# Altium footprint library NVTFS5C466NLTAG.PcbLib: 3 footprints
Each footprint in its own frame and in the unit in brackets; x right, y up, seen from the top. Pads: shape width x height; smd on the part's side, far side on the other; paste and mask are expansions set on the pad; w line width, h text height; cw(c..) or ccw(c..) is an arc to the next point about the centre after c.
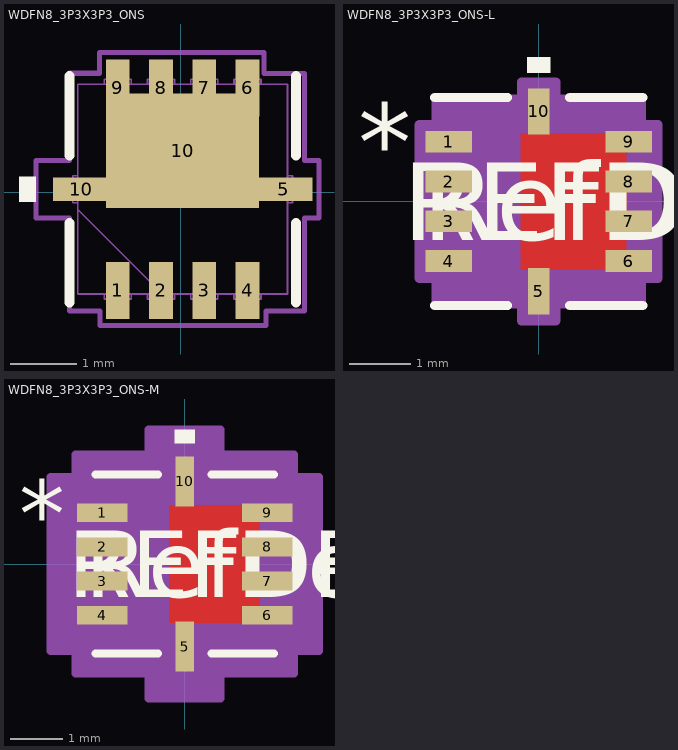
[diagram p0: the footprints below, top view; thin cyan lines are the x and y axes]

## WDFN8_3P3X3P3_ONS [mm]
pads (11):
  rect 0.356x0.859 smd paste+0 mask+0: 1(-0.948,-1.474) 2(-0.298,-1.474) 3(0.352,-1.474) 4(1.002,-1.474) 6(1.002,1.569) 7(0.352,1.569) 8(-0.298,1.569) 9(-0.948,1.569)
  rect 0.859x0.356 smd paste+0 mask+0: 5(1.548,0.047) 10(-1.495,0.047)
  rect 2.3x1.725 smd: 10(0.025,0.625)
Top Overlay:
  region: -2.178,0.238 -2.178,-0.143 -2.432,-0.143 -2.432,0.238
  lines w0.152: -1.675,-1.655 -1.675,-0.464 ; -1.675,0.558 -1.675,1.749 ; 1.728,-1.655 1.728,-0.464 ; 1.728,0.558 1.728,1.749
Top Paste:
  region: 1.144,-0.245 -1.091,-0.245 -1.091,1.482 1.144,1.482
Top Solder:
  region: 1.144,-0.245 -1.091,-0.245 -1.091,1.482 1.144,1.482
Mechanical 13:
  lines w0.025: -1.548,-0.258 -0.278,-1.528 ; -1.624,-0.156 -1.548,-0.156 -1.548,0.25 -1.624,0.25 -1.624,-0.156 ; -1.548,-1.528 -1.548,1.622 1.601,1.622 1.601,-1.528 -1.548,-1.528 ; -1.152,-1.604 -1.152,-1.528 -0.745,-1.528 -0.745,-1.604 -1.152,-1.604 ; -1.152,1.622 -0.745,1.622 -0.745,1.698 -1.152,1.698 -1.152,1.622 ; -0.502,-1.604 -0.502,-1.528 -0.095,-1.528 -0.095,-1.604 -0.502,-1.604 ; -0.502,1.622 -0.502,1.698 -0.095,1.698 -0.095,1.622 -0.502,1.622 ; 0.148,-1.604 0.148,-1.528 0.555,-1.528 0.555,-1.604 0.148,-1.604 ; 0.148,1.622 0.148,1.698 0.555,1.698 0.555,1.622 0.148,1.622 ; 0.798,-1.604 0.798,-1.528 1.205,-1.528 1.205,-1.604 0.798,-1.604 ; 0.798,1.622 0.798,1.698 1.205,1.698 1.205,1.622 0.798,1.622 ; 1.601,-0.156 1.601,0.25 1.678,0.25 1.678,-0.156 1.601,-0.156
Mechanical 15:
  lines w0.076: -2.178,-0.385 -1.675,-0.385 -1.675,-1.782 -1.213,-1.782 -1.213,-2 1.28,-2 1.28,-1.782 1.855,-1.782 1.855,-0.385 2.075,-0.385 2.075,0.479 1.855,0.479 1.855,1.786 1.25,1.786 1.25,2.1 -1.225,2.1 -1.225,1.789 -1.675,1.789 -1.675,0.479 -2.178,0.479 -2.178,-0.385
3D body "WDFN8_3P3X3P3_ONS.step": height 0.81, standoff 0, extent -1.624,-1.604 1.678,1.698

## WDFN8_3P3X3P3_ONS-L [mm]
pads (10):
  rect 0.759x0.356 smd paste+0 mask+0: 1(-1.472,0.975) 2(-1.472,0.325) 3(-1.472,-0.325) 4(-1.472,-0.975) 6(1.472,-0.975) 7(1.472,-0.325) 8(1.472,0.325) 9(1.472,0.975)
  rect 0.356x0.759 smd paste+0 mask+0: 5(0,-1.472) 10(0,1.472)
Top Layer:
  region: -0.292,-1.118 -0.292,1.118 1.435,1.118 1.435,-1.118
Top Overlay:
  region: 0.191,2.105 -0.191,2.105 -0.191,2.359 0.191,2.359
  lines w0.152: -1.702,-1.702 -0.511,-1.702 ; -1.702,1.702 -0.511,1.702 ; 0.511,-1.702 1.702,-1.702 ; 0.511,1.702 1.702,1.702
  text "*" at -2.956,0.34 h1.27
  text "RefDes" at -1.905,-0.635 h1.27
  text "REFDES" at -2.222,-0.635 h1.27
Top Paste:
  region: -0.292,-1.118 -0.292,1.118 1.435,1.118 1.435,-1.118
Top Solder:
  region: -0.292,-1.118 -0.292,1.118 1.435,1.118 1.435,-1.118
Mechanical 13:
  lines w0.025: -1.575,0.305 -0.305,1.575 ; -1.651,-1.178 -1.651,-0.772 -1.575,-0.772 -1.575,-1.178 -1.651,-1.178 ; -1.651,-0.528 -1.651,-0.122 -1.575,-0.122 -1.575,-0.528 -1.651,-0.528 ; -1.651,0.122 -1.651,0.528 -1.575,0.528 -1.575,0.122 -1.651,0.122 ; -1.651,0.772 -1.651,1.178 -1.575,1.178 -1.575,0.772 -1.651,0.772 ; -1.575,-1.575 1.575,-1.575 1.575,1.575 -1.575,1.575 -1.575,-1.575 ; -0.203,-1.651 -0.203,-1.575 0.203,-1.575 0.203,-1.651 -0.203,-1.651 ; -0.203,1.575 0.203,1.575 0.203,1.651 -0.203,1.651 -0.203,1.575 ; 1.575,-1.178 1.575,-0.772 1.651,-0.772 1.651,-1.178 1.575,-1.178 ; 1.575,-0.528 1.575,-0.122 1.651,-0.122 1.651,-0.528 1.575,-0.528 ; 1.575,0.122 1.575,0.528 1.651,0.528 1.651,0.122 1.575,0.122 ; 1.575,0.772 1.575,1.178 1.651,1.178 1.651,0.772 1.575,0.772
  text "*" at -0.622,0.34 h1.27
  text "RefDes2" at -2.222,-0.635 h1.27
Mechanical 15:
  region: -0.28,-1.676 -1.676,-1.676 -1.676,-1.255 -1.953,-1.255 -1.953,1.255 -1.676,1.255 -1.676,1.676 -0.28,1.676 -0.28,1.953 0.28,1.953 0.28,1.676 1.676,1.676 1.676,1.255 1.953,1.255 1.953,-1.255 1.676,-1.255 1.676,-1.676 0.28,-1.676 0.28,-1.953 -0.28,-1.953
  lines w0.152: -1.953,-1.255 -1.676,-1.255 -1.676,-1.676 -0.28,-1.676 -0.28,-1.953 0.28,-1.953 0.28,-1.676 1.676,-1.676 1.676,-1.255 1.953,-1.255 1.953,1.255 1.676,1.255 1.676,1.676 0.28,1.676 0.28,1.953 -0.28,1.953 -0.28,1.676 -1.676,1.676 -1.676,1.255 -1.953,1.255 -1.953,-1.255
3D body "WDFN8_3P3X3P3_ONS.step": height 0.81, standoff 0, extent -1.651,-1.651 1.651,1.651

## WDFN8_3P3X3P3_ONS-M [mm]
pads (10):
  rect 0.959x0.356 smd paste+0 mask+0: 1(-1.572,0.975) 2(-1.572,0.325) 3(-1.572,-0.325) 4(-1.572,-0.975) 6(1.572,-0.975) 7(1.572,-0.325) 8(1.572,0.325) 9(1.572,0.975)
  rect 0.356x0.959 smd paste+0 mask+0: 5(0,-1.572) 10(0,1.572)
Top Layer:
  region: -0.292,-1.118 -0.292,1.118 1.435,1.118 1.435,-1.118
Top Overlay:
  region: 0.191,2.305 -0.191,2.305 -0.191,2.559 0.191,2.559
  lines w0.152: -1.702,-1.702 -0.511,-1.702 ; -1.702,1.702 -0.511,1.702 ; 0.511,-1.702 1.702,-1.702 ; 0.511,1.702 1.702,1.702
  text "*" at -3.156,0.34 h1.27
  text "RefDes" at -1.905,-0.635 h1.27
  text "REFDES" at -2.222,-0.635 h1.27
Top Paste:
  region: -0.292,-1.118 -0.292,1.118 1.435,1.118 1.435,-1.118
Top Solder:
  region: -0.292,-1.118 -0.292,1.118 1.435,1.118 1.435,-1.118
Mechanical 13:
  lines w0.025: -1.575,0.305 -0.305,1.575 ; -1.651,-1.178 -1.651,-0.772 -1.575,-0.772 -1.575,-1.178 -1.651,-1.178 ; -1.651,-0.528 -1.651,-0.122 -1.575,-0.122 -1.575,-0.528 -1.651,-0.528 ; -1.651,0.122 -1.651,0.528 -1.575,0.528 -1.575,0.122 -1.651,0.122 ; -1.651,0.772 -1.651,1.178 -1.575,1.178 -1.575,0.772 -1.651,0.772 ; -1.575,-1.575 1.575,-1.575 1.575,1.575 -1.575,1.575 -1.575,-1.575 ; -0.203,-1.651 -0.203,-1.575 0.203,-1.575 0.203,-1.651 -0.203,-1.651 ; -0.203,1.575 0.203,1.575 0.203,1.651 -0.203,1.651 -0.203,1.575 ; 1.575,-1.178 1.575,-0.772 1.651,-0.772 1.651,-1.178 1.575,-1.178 ; 1.575,-0.528 1.575,-0.122 1.651,-0.122 1.651,-0.528 1.575,-0.528 ; 1.575,0.122 1.575,0.528 1.651,0.528 1.651,0.122 1.575,0.122 ; 1.575,0.772 1.575,1.178 1.651,1.178 1.651,0.772 1.575,0.772
  text "*" at -0.622,0.34 h1.27
  text "RefDes2" at -2.222,-0.635 h1.27
Mechanical 15:
  region: -0.686,-2.083 -2.083,-2.083 -2.083,-1.661 -2.559,-1.661 -2.559,1.661 -2.083,1.661 -2.083,2.083 -0.686,2.083 -0.686,2.559 0.686,2.559 0.686,2.083 2.083,2.083 2.083,1.661 2.559,1.661 2.559,-1.661 2.083,-1.661 2.083,-2.083 0.686,-2.083 0.686,-2.559 -0.686,-2.559
  lines w0.152: -2.559,-1.661 -2.083,-1.661 -2.083,-2.083 -0.686,-2.083 -0.686,-2.559 0.686,-2.559 0.686,-2.083 2.083,-2.083 2.083,-1.661 2.559,-1.661 2.559,1.661 2.083,1.661 2.083,2.083 0.686,2.083 0.686,2.559 -0.686,2.559 -0.686,2.083 -2.083,2.083 -2.083,1.661 -2.559,1.661 -2.559,-1.661
3D body "WDFN8_3P3X3P3_ONS.step": height 0.81, standoff 0, extent -1.651,-1.651 1.651,1.651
